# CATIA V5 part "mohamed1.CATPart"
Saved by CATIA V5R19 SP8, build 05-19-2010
Part number: levier
Bounding box of the stored display mesh (mm): x 0 to 44, y -50 to 136, z -35 to 35
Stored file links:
  C:\Documents and Settings\msamadi\Bureau\projet 2 vendredi\mohamed1.CATPart
  C:\Documents and Settings\msamadi\Bureau\Product1.CATProduct
  C:\Documents and Settings\msamadi\Bureau\piéce2\Productfinal.CATProduct
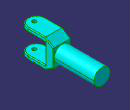
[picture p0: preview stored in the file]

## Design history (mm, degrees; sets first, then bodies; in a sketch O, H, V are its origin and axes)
Parameters
  LENGTH = 10 mm
Body1 (main body)
  Sketch1 on yz-plane, origin (0, 0, 0), H (0, 1, 0), V (0, 0, 1)
    line L1 (-50, 25) -> (15, 25)
    line L2 (15, 25) -> (15, -25)
    line L3 (15, -25) -> (-50, -25)
    line L4 (-50, -25) -> (-50, -35)
    line L5 (-50, -35) -> (15, -35)
    line L6 (15, -35) -> (36, -22)
    point P7 (36, -22)
    line L7 (36, -22) -> (36, 22)
    point P8 (36, 22)
    line L8 (36, 22) -> (15, 35)
    point P9 (15, 35)
    line L9 (15, 35) -> (-50, 35)
    point P10 (-50, 35)
    line L10 (-50, 35) -> (-50, 25)
    length L7 = 44 {= LENGTH *4.4}
    distance L3 L1 = 50 {= LENGTH *5}
    distance L3 H = 25 {= LENGTH *2.5}
    distance L5 H = 35 {= LENGTH *3.5}
    distance L2 V = 15 {= LENGTH *1.5}
    distance L7 V = 36 {= LENGTH *3.6}
    distance P8 L9 = 13 {= LENGTH *1.3}
    length L9 = 65 {= LENGTH *6.5}
    length L5 = 65 {= LENGTH *6.5}
    distance P7 H = 22 {= LENGTH *2.2}
    horizontal: L1 H, L3 H, L5 H, L9 H
    vertical: L2 V, L4 V, L7 V, L10 V
    coincidence: P9 L2, P10 L4, L10 L4
  Pad1: profile Sketch1, direction (1, 0, 0), length 44 {= LENGTH *4.4}
  Sketch2 on face of Pad1 from Sketch1.L9, origin (32.3992, -3.637, 35), H (1, 0, 0), V (0, 1, 0)
    point P1 (-9.8992, -30)
    reference projected line E1 (-32.3992, 18.637) -> (-32.3992, -46.363) from edge [start face of Pad1 | face of Pad1 from Sketch1.L9]
    distance P1 E1 = 22.5 {= LENGTH *2.25}
    distance H P1 = 30 {= LENGTH *3}
  Hole1: placed by Sketch2, at (22.5, -33.637, 35) direction (0, 0, -1), diameter 10 {= LENGTH *1}, through (limit type 3), offset 0 {= LENGTH *0}
  Fillet1: radius 22 {= LENGTH *2.2}, on edge [start face of Pad1 | face of Pad1 from Sketch1.L4]
  Fillet2: radius 22 {= LENGTH *2.2}, on edge [face of Pad1 from Sketch1.L4 | end face of Pad1]
  Fillet3: radius 22 {= LENGTH *2.2}, on edge [start face of Pad1 | face of Pad1 from Sketch1.L10]
  Fillet4: radius 22 {= LENGTH *2.2}, on edge [face of Pad1 from Sketch1.L10 | end face of Pad1]
  Sketch3 on face of Pad1 from Sketch1.L7, origin (0, 36, 0), H (-1, 0, 0), V (0, 0, 1)
    circle A1 centre (-22, 0) radius 20
    point P1 (-22, 0)
    distance P1 V = 22 {= LENGTH *2.2}
    distance P1 A1 = 20 {= LENGTH *2}
    coincidence: P1 H
  Pad2: profile Sketch3, direction (0, 1, 0), length 100 {= LENGTH *10}
  Sketch4 on face of Pad1 from Sketch1.L7, origin (0, 36, 0), H (-1, 0, 0), V (0, 0, 1)
    reference projected line E1 (0, 22) -> (-42, 22) from edge [face of Pad1 from Sketch1.L8 | face of Pad1 from Sketch1.L7]
    reference projected line E2 (0, -30) -> (0, 30) from Sketch1
    angle E1 E2 = 90 (reference)
  Fillet5: radius 2 {= LENGTH *0.2}, on start face of Pad1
